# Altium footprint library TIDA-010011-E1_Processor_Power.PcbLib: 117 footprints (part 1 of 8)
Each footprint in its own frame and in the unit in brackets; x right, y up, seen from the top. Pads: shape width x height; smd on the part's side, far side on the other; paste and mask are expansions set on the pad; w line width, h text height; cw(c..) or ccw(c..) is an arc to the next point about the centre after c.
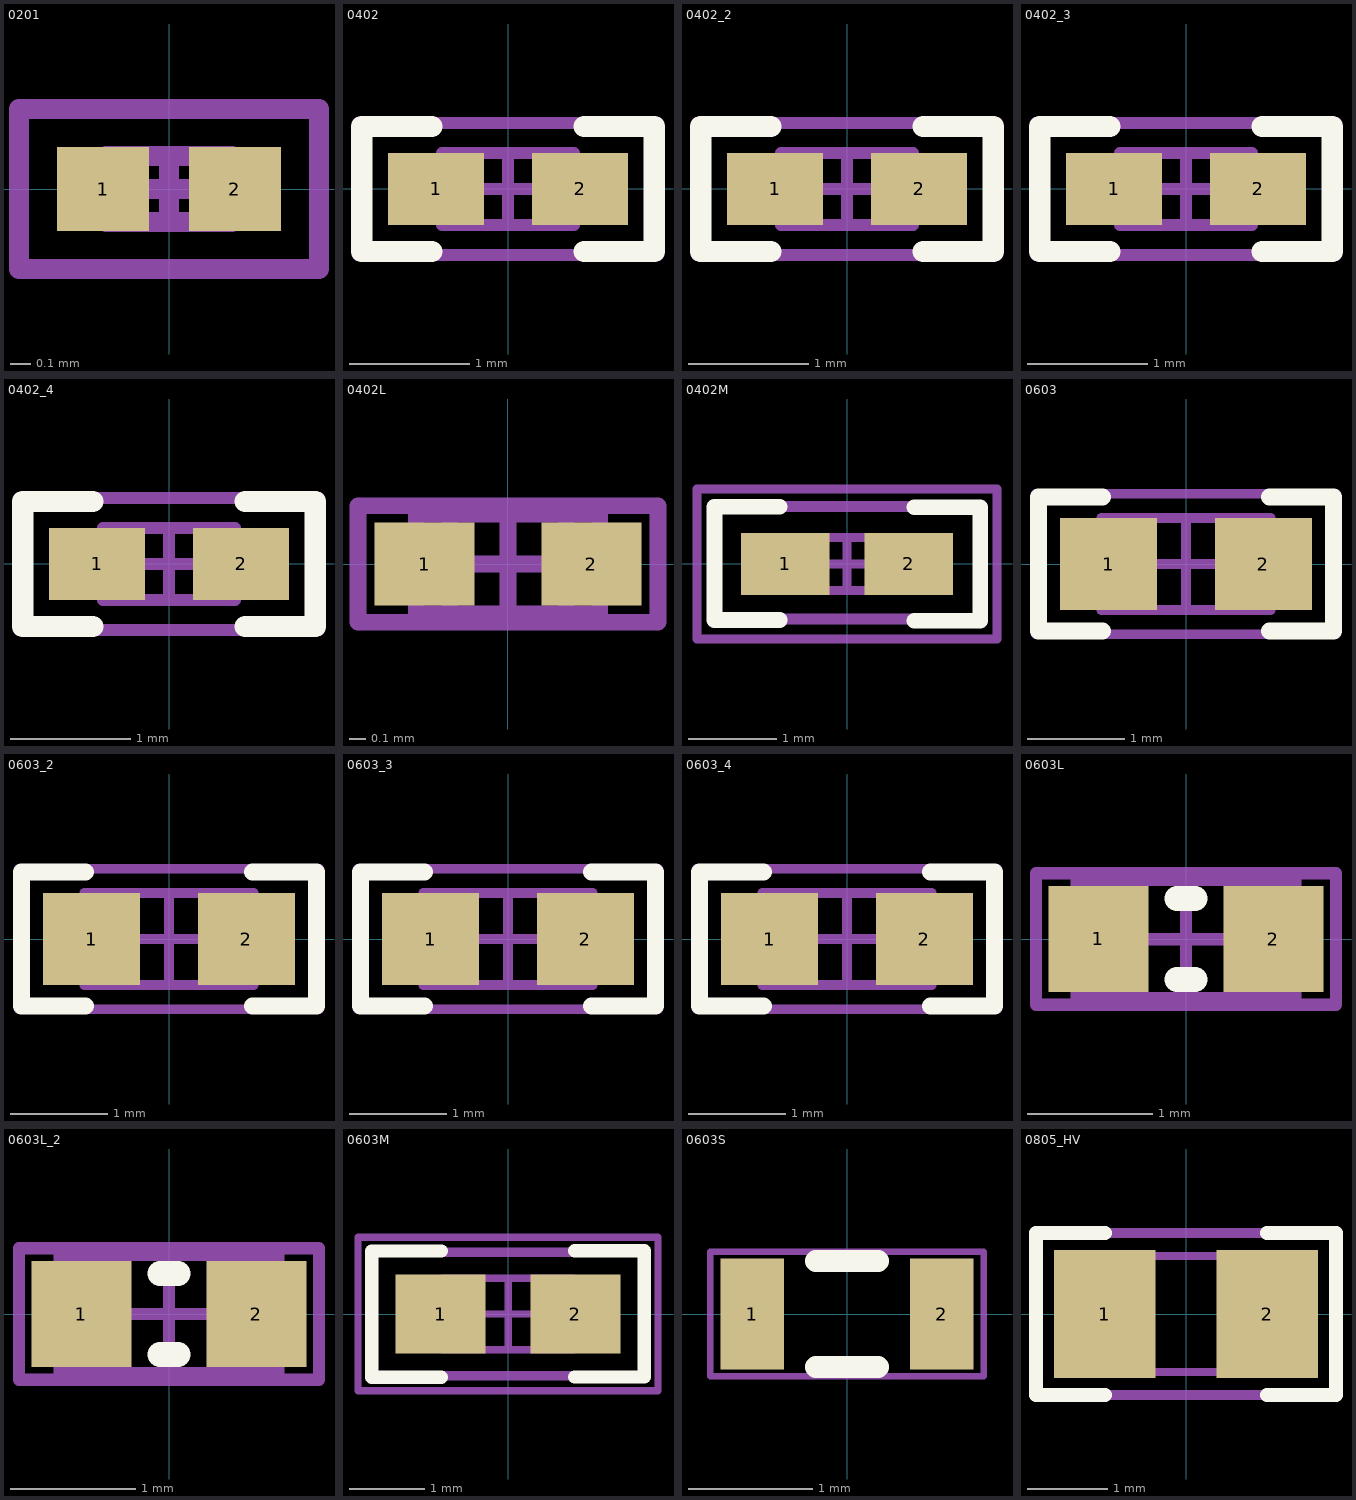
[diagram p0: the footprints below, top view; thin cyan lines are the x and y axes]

## 0201 [mm] "Data from Kemet datasheet CC101_COM dated 7/28/11"
height 0.26
pads (2):
  rect 0.46x0.42 smd mask+0.048: 1(-0.33,0) 2(0.33,0)
Mechanical 5:
  lines w0.1: -0.75,-0.4 -0.75,0.4 0.75,0.4 0.75,-0.4 -0.75,-0.4
  text ".Designator" at -2.692,-0.102 h0.51
Mechanical 13:
  lines w0.1: -0.215,-0.165 -0.215,0.165 ; 0.215,-0.165 0.215,0.165 ; -0.315,-0.165 0.315,-0.165 0.315,0.165 -0.315,0.165 -0.315,-0.165
Mechanical 15:
  lines w0.1: -0.165,0 0.165,0 ; 0,-0.165 0,0.165 ; -0.75,-0.4 0.75,-0.4 0.75,0.4 -0.75,0.4 -0.75,-0.4
3D body: height 0.26, standoff 0, extent 0.216,-0.164 0.314,0.164
3D body: height 0.26, standoff 0, extent -0.214,-0.164 0.214,0.164
3D body: height 0.26, standoff 0, extent -0.314,-0.164 -0.216,0.164

## 0402 [mm] "0402 from SM-752 data"
height 0.6
pads (2):
  rect 0.8x0.6 smd: 1(-0.6,0) 2(0.6,0)
Top Overlay:
  lines w0.178: -0.635,-0.521 -1.219,-0.521 -1.219,0.521 -0.635,0.521 ; 0.635,-0.521 1.219,-0.521 1.219,0.521 0.635,0.521
Mechanical 5:
  lines w0.1: -1.25,-0.55 1.25,-0.55 1.25,0.55 -1.25,0.55 -1.25,-0.55
  text ".Designator" at 0.781,0.33 h0.51
Mechanical 13:
  lines w0.1: -0.35,-0.3 -0.35,0.3 ; 0.35,-0.3 0.35,0.3 ; -0.55,-0.3 -0.55,0.3 0.55,0.3 0.55,-0.3 -0.55,-0.3
Mechanical 15:
  lines w0.1: -0.3,0 0.3,0 ; 0,-0.3 0,0.3 ; -1.25,-0.55 -1.25,0.55 1.25,0.55 1.25,-0.55 -1.25,-0.55
3D body: height 0.6, standoff 0, extent -0.549,-0.299 -0.351,0.299
3D body: height 0.6, standoff 0, extent -0.349,-0.299 0.349,0.299
3D body: height 0.6, standoff 0, extent 0.351,-0.299 0.549,0.299

## 0402_2 [mm]
pads (2):
  rect 0.8x0.6 smd: 1(-0.6,0) 2(0.6,0)
Top Overlay:
  lines w0.178: -0.635,-0.521 -1.219,-0.521 -1.219,0.521 -0.635,0.521 ; 0.635,-0.521 1.219,-0.521 1.219,0.521 0.635,0.521
Mechanical 5:
  lines w0.1: -1.25,-0.55 1.25,-0.55 1.25,0.55 -1.25,0.55 -1.25,-0.55
  text ".Designator" at 0.991,0.305 h0.51
Mechanical 13:
  lines w0.1: -0.35,-0.3 -0.35,0.3 ; 0.35,-0.3 0.35,0.3 ; -0.55,-0.3 -0.55,0.3 0.55,0.3 0.55,-0.3 -0.55,-0.3
Mechanical 15:
  lines w0.1: -0.3,0 0.3,0 ; 0,-0.3 0,0.3 ; -1.25,-0.55 -1.25,0.55 1.25,0.55 1.25,-0.55 -1.25,-0.55
3D body: height 0.6, standoff 0, extent -0.549,-0.299 -0.351,0.299
3D body: height 0.6, standoff 0, extent -0.349,-0.299 0.349,0.299
3D body: height 0.6, standoff 0, extent 0.351,-0.299 0.549,0.299

## 0402_3 [mm]
pads (2):
  rect 0.8x0.6 smd: 1(-0.6,0) 2(0.6,0)
Top Overlay:
  lines w0.178: -0.635,-0.521 -1.219,-0.521 -1.219,0.521 -0.635,0.521 ; 0.635,-0.521 1.219,-0.521 1.219,0.521 0.635,0.521
Mechanical 5:
  lines w0.1: -1.25,-0.55 1.25,-0.55 1.25,0.55 -1.25,0.55 -1.25,-0.55
  text ".Designator" at 0.438,0.279 h0.51
Mechanical 13:
  lines w0.1: -0.35,-0.3 -0.35,0.3 ; 0.35,-0.3 0.35,0.3 ; -0.55,-0.3 -0.55,0.3 0.55,0.3 0.55,-0.3 -0.55,-0.3
Mechanical 15:
  lines w0.1: -0.3,0 0.3,0 ; 0,-0.3 0,0.3 ; -1.25,-0.55 -1.25,0.55 1.25,0.55 1.25,-0.55 -1.25,-0.55
3D body: height 0.6, standoff 0, extent -0.549,-0.299 -0.351,0.299
3D body: height 0.6, standoff 0, extent -0.349,-0.299 0.349,0.299
3D body: height 0.6, standoff 0, extent 0.351,-0.299 0.549,0.299

## 0402_4 [mm]
pads (2):
  rect 0.8x0.6 smd: 1(-0.6,0) 2(0.6,0)
Top Overlay:
  lines w0.178: -0.635,-0.521 -1.219,-0.521 -1.219,0.521 -0.635,0.521 ; 0.635,-0.521 1.219,-0.521 1.219,0.521 0.635,0.521
Mechanical 5:
  lines w0.1: -1.25,-0.55 -1.25,0.55 1.25,0.55 1.25,-0.55 -1.25,-0.55
  text ".Designator" at -0.927,-0.225 h0.51
Mechanical 13:
  lines w0.1: -0.35,-0.3 -0.35,0.3 ; 0.35,-0.3 0.35,0.3 ; -0.55,-0.3 0.55,-0.3 0.55,0.3 -0.55,0.3 -0.55,-0.3
Mechanical 15:
  lines w0.1: -0.3,0 0.3,0 ; 0,-0.3 0,0.3 ; -1.25,-0.55 1.25,-0.55 1.25,0.55 -1.25,0.55 -1.25,-0.55
3D body: height 0.6, standoff 0, extent 0.351,-0.299 0.549,0.299
3D body: height 0.6, standoff 0, extent -0.349,-0.299 0.349,0.299
3D body: height 0.6, standoff 0, extent -0.549,-0.299 -0.351,0.299

## 0402L [mm] "0402 from SM-752 data"
height 0.6
pads (2):
  rect 0.6x0.5 smd: 1(-0.5,0) 2(0.5,0)
Mechanical 5:
  lines w0.1: -0.9,-0.35 0.9,-0.35 0.9,0.35 -0.9,0.35 -0.9,-0.35
  text ".Designator" at 1.981,0.261 h0.51
Mechanical 13:
  lines w0.1: -0.35,-0.3 -0.35,0.3 ; 0.35,-0.3 0.35,0.3 ; -0.55,-0.3 -0.55,0.3 0.55,0.3 0.55,-0.3 -0.55,-0.3
Mechanical 15:
  lines w0.1: -0.3,0 0.3,0 ; 0,-0.3 0,0.3 ; -0.9,-0.35 -0.9,0.35 0.9,0.35 0.9,-0.35 -0.9,-0.35
3D body: height 0.6, standoff 0, extent -0.549,-0.299 -0.351,0.299
3D body: height 0.6, standoff 0, extent -0.349,-0.299 0.349,0.299
3D body: height 0.6, standoff 0, extent 0.351,-0.299 0.549,0.299

## 0402M [mm] "0402 from SM-752 data"
height 0.6
pads (2):
  rect 1x0.7 smd: 1(-0.7,0) 2(0.7,0)
Top Overlay:
  lines w0.178: -1.501,-0.635 -0.762,-0.635 ; -1.501,-0.627 -1.501,0.63 ; -1.501,0.65 -0.762,0.65 ; 0.762,-0.643 1.511,-0.643 ; 0.762,0.643 1.511,0.643 ; 1.511,-0.622 1.511,0.635
Mechanical 5:
  lines w0.127: -1.5,-0.625 1.525,-0.625 1.525,0.65 -1.5,0.65 -1.5,-0.625
  text ".Designator" at 1.118,0.279 h0.51
Mechanical 13:
  lines w0.1: -0.35,-0.3 -0.35,0.3 ; 0.35,-0.3 0.35,0.3 ; -0.55,-0.3 0.55,-0.3 0.55,0.3 -0.55,0.3 -0.55,-0.3
Mechanical 15:
  lines w0.1: -0.3,0 0.3,0 ; 0,-0.3 0,0.3 ; -1.7,-0.85 1.7,-0.85 1.7,0.85 -1.7,0.85 -1.7,-0.85
3D body: height 0.6, standoff 0, extent 0.351,-0.299 0.549,0.299
3D body: height 0.6, standoff 0, extent -0.349,-0.299 0.349,0.299
3D body: height 0.6, standoff 0, extent -0.549,-0.299 -0.351,0.299

## 0603 [mm] "0603 from SM-752 data"
height 1
pads (2):
  rect 1x0.95 smd: 1(-0.8,0) 2(0.8,0)
Top Overlay:
  lines w0.178: -0.864,-0.691 -1.524,-0.691 -1.524,0.693 -0.864,0.693 ; 0.864,-0.691 1.524,-0.691 1.524,0.693 0.864,0.693
Mechanical 5:
  lines w0.1: -1.55,-0.725 1.55,-0.725 1.55,0.725 -1.55,0.725 -1.55,-0.725
  text ".Designator" at -0.965,-0.229 h0.51
Mechanical 13:
  lines w0.1: -0.55,-0.475 -0.55,0.475 ; 0.55,-0.475 0.55,0.475 ; -0.875,-0.475 -0.875,0.475 0.875,0.475 0.875,-0.475 -0.875,-0.475
Mechanical 15:
  lines w0.1: -0.475,0 0.475,0 ; 0,-0.475 0,0.475 ; -1.55,-0.725 -1.55,0.725 1.55,0.725 1.55,-0.725 -1.55,-0.725
3D body: height 1, standoff 0, extent 0.551,-0.474 0.874,0.474
3D body: height 1, standoff 0, extent -0.549,-0.474 0.549,0.474
3D body: height 1, standoff 0, extent -0.874,-0.474 -0.551,0.474

## 0603_2 [mm]
pads (2):
  rect 1x0.95 smd: 1(-0.8,0) 2(0.8,0)
Top Overlay:
  lines w0.178: -0.864,-0.691 -1.524,-0.691 -1.524,0.693 -0.864,0.693 ; 0.864,-0.691 1.524,-0.691 1.524,0.693 0.864,0.693
Mechanical 5:
  lines w0.1: -1.55,-0.725 1.55,-0.725 1.55,0.725 -1.55,0.725 -1.55,-0.725
  text ".Designator" at 0.889,0.305 h0.51
Mechanical 13:
  lines w0.1: -0.55,-0.475 -0.55,0.475 ; 0.55,-0.475 0.55,0.475 ; -0.875,-0.475 -0.875,0.475 0.875,0.475 0.875,-0.475 -0.875,-0.475
Mechanical 15:
  lines w0.1: -0.475,0 0.475,0 ; 0,-0.475 0,0.475 ; -1.55,-0.725 -1.55,0.725 1.55,0.725 1.55,-0.725 -1.55,-0.725
3D body: height 1, standoff 0, extent 0.551,-0.474 0.874,0.474
3D body: height 1, standoff 0, extent -0.549,-0.474 0.549,0.474
3D body: height 1, standoff 0, extent -0.874,-0.474 -0.551,0.474

## 0603_3 [mm]
pads (2):
  rect 1x0.95 smd: 1(-0.8,0) 2(0.8,0)
Top Overlay:
  lines w0.178: -0.864,-0.691 -1.524,-0.691 -1.524,0.693 -0.864,0.693 ; 0.864,-0.691 1.524,-0.691 1.524,0.693 0.864,0.693
Mechanical 5:
  lines w0.1: -1.55,-0.725 -1.55,0.725 1.55,0.725 1.55,-0.725 -1.55,-0.725
  text ".Designator" at 0.711,0.102 h0.51
Mechanical 13:
  lines w0.1: -0.55,-0.475 -0.55,0.475 ; 0.55,-0.475 0.55,0.475 ; -0.875,-0.475 0.875,-0.475 0.875,0.475 -0.875,0.475 -0.875,-0.475
Mechanical 15:
  lines w0.1: -0.475,0 0.475,0 ; 0,-0.475 0,0.475 ; -1.55,-0.725 1.55,-0.725 1.55,0.725 -1.55,0.725 -1.55,-0.725
3D body: height 1, standoff 0, extent -0.874,-0.474 -0.551,0.474
3D body: height 1, standoff 0, extent -0.549,-0.474 0.549,0.474
3D body: height 1, standoff 0, extent 0.551,-0.474 0.874,0.474

## 0603_4 [mm]
pads (2):
  rect 1x0.95 smd: 1(-0.8,0) 2(0.8,0)
Top Overlay:
  lines w0.178: -0.864,-0.691 -1.524,-0.691 -1.524,0.693 -0.864,0.693 ; 0.864,-0.691 1.524,-0.691 1.524,0.693 0.864,0.693
Mechanical 5:
  lines w0.1: -1.55,-0.725 1.55,-0.725 1.55,0.725 -1.55,0.725 -1.55,-0.725
  text ".Designator" at 0.66,0.279 h0.51
Mechanical 13:
  lines w0.1: -0.55,-0.475 -0.55,0.475 ; 0.55,-0.475 0.55,0.475 ; -0.875,-0.475 -0.875,0.475 0.875,0.475 0.875,-0.475 -0.875,-0.475
Mechanical 15:
  lines w0.1: -0.475,0 0.475,0 ; 0,-0.475 0,0.475 ; -1.55,-0.725 -1.55,0.725 1.55,0.725 1.55,-0.725 -1.55,-0.725
3D body: height 1, standoff 0, extent 0.551,-0.474 0.874,0.474
3D body: height 1, standoff 0, extent -0.549,-0.474 0.549,0.474
3D body: height 1, standoff 0, extent -0.874,-0.474 -0.551,0.474

## 0603L [mm] "0603 from SM-752 data"
height 1
pads (2):
  rect 0.8x0.85 smd: 1(-0.7,0) 2(0.7,0)
Top Overlay:
  lines w0.2: -0.071,-0.325 0.071,-0.325 ; -0.071,0.325 0.071,0.325
Mechanical 5:
  lines w0.1: -1.2,-0.525 1.2,-0.525 1.2,0.525 -1.2,0.525 -1.2,-0.525
  text ".Designator" at 0.929,0.34 h0.51
Mechanical 13:
  lines w0.1: -0.55,-0.475 -0.55,0.475 ; 0.55,-0.475 0.55,0.475 ; -0.875,-0.475 0.875,-0.475 0.875,0.475 -0.875,0.475 -0.875,-0.475
Mechanical 15:
  lines w0.1: -0.475,0 0.475,0 ; 0,-0.475 0,0.475 ; -1.2,-0.525 -1.2,0.525 1.2,0.525 1.2,-0.525 -1.2,-0.525
3D body: height 1, standoff 0, extent -0.874,-0.474 -0.551,0.474
3D body: height 1, standoff 0, extent -0.549,-0.474 0.549,0.474
3D body: height 1, standoff 0, extent 0.551,-0.474 0.874,0.474

## 0603L_2 [mm]
pads (2):
  rect 0.8x0.85 smd: 1(-0.7,0) 2(0.7,0)
Top Overlay:
  lines w0.2: -0.071,-0.325 0.071,-0.325 ; -0.071,0.325 0.071,0.325
Mechanical 5:
  lines w0.1: -1.2,-0.525 -1.2,0.525 1.2,0.525 1.2,-0.525 -1.2,-0.525
  text ".Designator" at -0.451,-0.232 h0.51
Mechanical 13:
  lines w0.1: -0.55,-0.475 -0.55,0.475 ; 0.55,-0.475 0.55,0.475 ; -0.875,-0.475 -0.875,0.475 0.875,0.475 0.875,-0.475 -0.875,-0.475
Mechanical 15:
  lines w0.1: -0.475,0 0.475,0 ; 0,-0.475 0,0.475 ; -1.2,-0.525 1.2,-0.525 1.2,0.525 -1.2,0.525 -1.2,-0.525
3D body: height 1, standoff 0, extent 0.551,-0.474 0.874,0.474
3D body: height 1, standoff 0, extent -0.549,-0.474 0.549,0.474
3D body: height 1, standoff 0, extent -0.874,-0.474 -0.551,0.474

## 0603M [mm] "0603 from SM-752 data"
height 1
pads (2):
  rect 1.2x1.05 smd: 1(-0.9,0) 2(0.9,0)
Top Overlay:
  lines w0.178: -1.819,0.805 -1.819,-0.843 -0.889,-0.843 ; -1.819,0.841 -0.889,0.841 ; 0.889,-0.841 1.819,-0.841 ; 0.889,0.843 1.819,0.843 1.819,-0.805
Mechanical 5:
  lines w0.127: -1.825,-0.825 -1.825,0.825 1.825,0.825 1.825,-0.825 -1.825,-0.825
  text ".Designator" at 1.067,0.178 h0.51
Mechanical 13:
  lines w0.1: -0.55,-0.475 -0.55,0.475 ; 0.55,-0.475 0.55,0.475 ; -0.875,-0.475 -0.875,0.475 0.875,0.475 0.875,-0.475 -0.875,-0.475
Mechanical 15:
  lines w0.1: -0.475,0 0.475,0 ; 0,-0.475 0,0.475 ; -2,-1.025 -2,1.025 2,1.025 2,-1.025 -2,-1.025
3D body: height 1, standoff 0, extent 0.551,-0.474 0.874,0.474
3D body: height 1, standoff 0, extent -0.549,-0.474 0.549,0.474
3D body: height 1, standoff 0, extent -0.874,-0.474 -0.551,0.474

## 0603S [mil]
height 39.37
pads (2):
  rect 20x35 smd: 1(-30,0) 2(30,0)
Top Overlay:
  lines w7: -9.84,-16.73 9.84,-16.73 ; -9.84,16.73 9.84,16.73
Mechanical 5:
  lines w1.97: -43.31,-19.68 43.31,-19.68 43.31,19.68 -43.31,19.68 -43.31,-19.68
  text ".Designator" at -23.1,-8.65 h20
3D body: height 39.37, standoff 0, extent -34.43,-18.68 -21.67,18.68
3D body: height 39.37, standoff 0, extent -21.63,-18.68 21.63,18.68
3D body: height 39.37, standoff 0, extent 21.67,-18.68 34.43,18.68

## 0805_HV [mil] "0805 with 30mil clearance between pads"
height 57.09
pads (2):
  rect 50x63 smd: 1(-40,0) 2(40,0)
Top Overlay:
  lines w7: -40,-40 -74,-40 -74,0 -74,40 -40,40 ; 40,-40 74,-40 74,0 74,40 40,40
Mechanical 5:
  lines w5: -74,-40 74,-40 74,40 -74,40 -74,-40
  text ".Designator" at -30,-12 h20
Mechanical 13:
  lines w3.94: -25.59,-28.54 -25.59,28.54 ; 25.59,-28.54 25.59,28.54 ; -43.31,-28.54 43.31,-28.54 43.31,28.54 -43.31,28.54 -43.31,-28.54
3D body: height 57.09, standoff 0, extent -43.29,-28.52 -25.61,28.52
3D body: height 57.09, standoff 0, extent -25.57,-28.52 25.57,28.52
3D body: height 57.09, standoff 0, extent 25.61,-28.52 43.29,28.52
